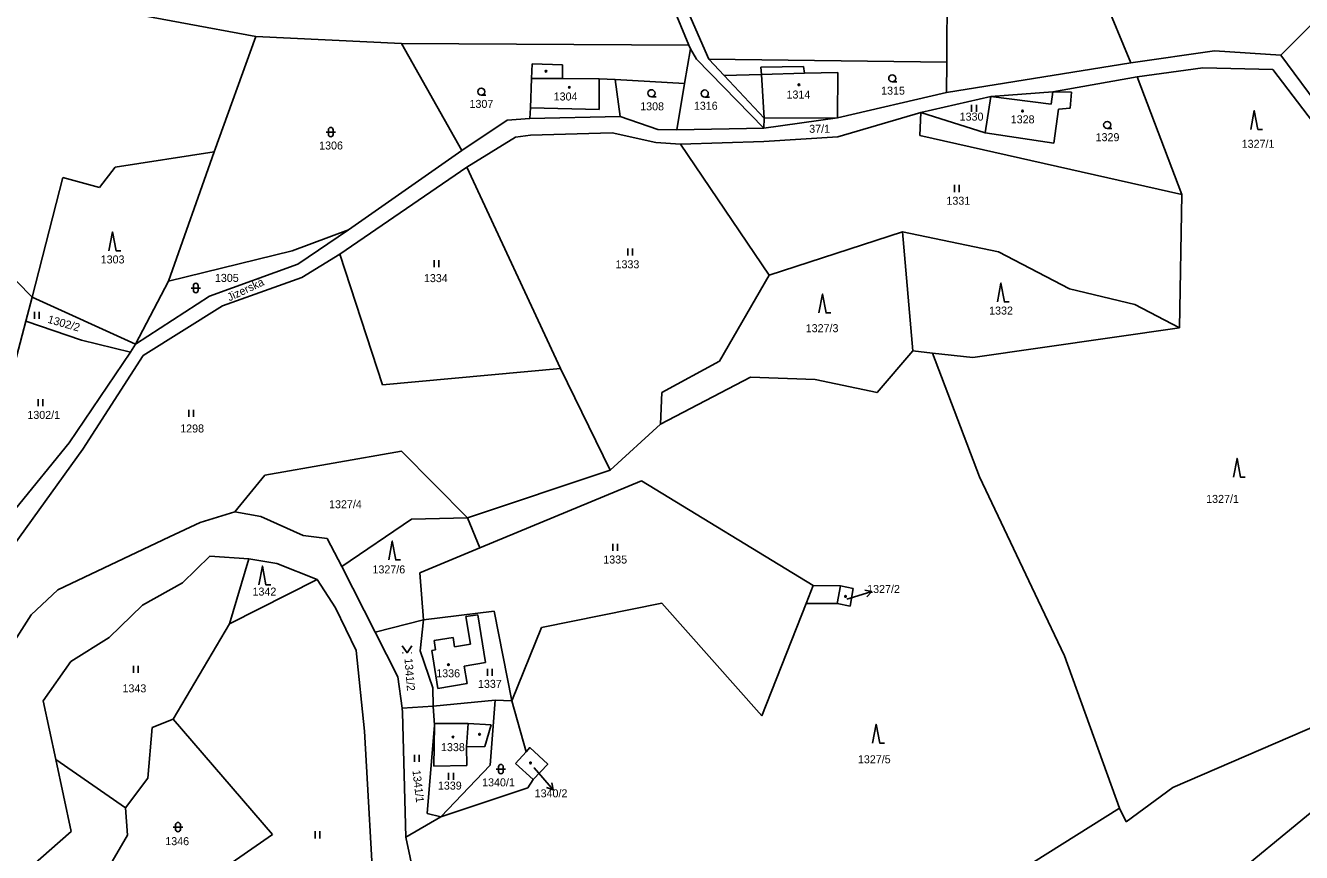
# Model space of a CAD drawing. Extents: x -670359 to -668019, y -978807 to -976674.
# Drawn here: x -669846.5 to -669575.5, y -978118.6 to -977942.9 of the extents above; entities that cross this region are included whole.
import ezdxf

# ---------------------------------------------------------------- set-up
doc = ezdxf.new("R2010")
doc.units = 0
for name, color, linetype in [('Hranice parcel', 7, 'Continuous'), ('Parcelní čísla', 7, 'Continuous'), ('Pop  PČ popisy', 7, 'Continuous'), ('Vnitřní kresba', 7, 'Continuous'), ('Značky budov', 7, 'Continuous'), ('Značky kultur', 7, 'Continuous')]:
    doc.layers.add(name, color=color, linetype=linetype)

msp = doc.modelspace()

# ---------------------------------------------------------------- linework, layer by layer
at = {"layer": 'Hranice parcel'}
for p, q in [((-669749.99, -978053.86), (-669715.71, -978039.65)), ((-669749.99, -978053.86), (-669752.65, -978047.5)), ((-669762.74, -978059.14), (-669749.99, -978053.86)), ((-669752.97, -978068.48), (-669750.42, -978068.07)), ((-669751.98, -978074.33), (-669752.97, -978068.48)), ((-669750.42, -978068.07), (-669748.8, -978078.23)), ((-669759.75, -978073.55), (-669755.71, -978072.94)), ((-669759.43, -978075.56), (-669759.75, -978073.55)), ((-669755.71, -978072.94), (-669755.39, -978074.89)), ((-669755.39, -978074.89), (-669751.98, -978074.33)), ((-669759.43, -978075.56), (-669760.25, -978075.66)), ((-669760.25, -978075.66), (-669758.93, -978083.72)), ((-669748.8, -978078.23), (-669753.36, -978079.01)), ((-669753.36, -978079.01), (-669752.75, -978082.68)), ((-669752.75, -978082.68), (-669758.93, -978083.72))]:
    msp.add_line(p, q, dxfattribs=at)
for points in [[(-669715.01, -977924.37), (-669705.6, -977947.07)], [(-669712.05, -977925.47), (-669701.36, -977950.02)], [(-669561.67, -977930.85), (-669579.87, -977949.13)], [(-669650.74, -977934.54), (-669650.81, -977950.68)], [(-669617.62, -977936.58), (-669611.71, -977950.77)], [(-669829.77, -977939.28), (-669797.59, -977945.16)], [(-669806.49, -977969.67), (-669797.59, -977945.16)], [(-669797.59, -977945.16), (-669766.63, -977946.66)], [(-669753.87, -977969.43), (-669766.63, -977946.66)], [(-669766.63, -977946.66), (-669705.6, -977947.07)], [(-669705.29, -977947.81), (-669705.6, -977947.07)], [(-669706.53, -977955.17), (-669705.29, -977947.81)], [(-669704, -977950.04), (-669705.29, -977947.81)], [(-669689.68, -977964.66), (-669704, -977950.04)], [(-669701.36, -977950.02), (-669698.1, -977953.5)], [(-669650.81, -977950.68), (-669701.36, -977950.02)], [(-669593.97, -977948.26), (-669611.71, -977950.77)], [(-669579.87, -977949.13), (-669593.97, -977948.26)], [(-669579.87, -977949.13), (-669571.19, -977960.9)], [(-669739.05, -977954.1), (-669738.94, -977950.97)], [(-669738.94, -977950.97), (-669732.46, -977951.25)], [(-669732.44, -977954.12), (-669732.46, -977951.25)], [(-669681.28, -977951.58), (-669690.31, -977951.71)], [(-669690.31, -977951.71), (-669690.21, -977953.28)], [(-669681.03, -977953.02), (-669681.28, -977951.58)], [(-669673.99, -977952.82), (-669681.03, -977953.02)], [(-669674.02, -977962.49), (-669673.99, -977952.82)], [(-669650.86, -977957.07), (-669650.81, -977950.68)], [(-669611.71, -977950.77), (-669650.86, -977957.07)], [(-669596.43, -977951.87), (-669610.41, -977953.79)], [(-669581.59, -977952.23), (-669596.43, -977951.87)], [(-669581.59, -977952.23), (-669572.03, -977964.73)], [(-669739.29, -977960.32), (-669739.05, -977954.1)], [(-669724.69, -977954.16), (-669732.44, -977954.12)], [(-669721.25, -977954.3), (-669724.69, -977954.16)], [(-669720.24, -977962.2), (-669721.25, -977954.3)], [(-669721.25, -977954.3), (-669706.53, -977955.17)], [(-669708.15, -977965.01), (-669706.53, -977955.17)], [(-669690.21, -977953.28), (-669698.1, -977953.5)], [(-669698.1, -977953.5), (-669689.61, -977962.58)], [(-669610.41, -977953.79), (-669628.31, -977956.94)], [(-669610.41, -977953.79), (-669600.92, -977978.75)], [(-669650.86, -977957.07), (-669674.02, -977962.49)], [(-669641.5, -977957.98), (-669656.35, -977961.34)], [(-669641.5, -977957.98), (-669642.65, -977965.65)], [(-669628.31, -977956.94), (-669641.5, -977957.98)], [(-669628.31, -977956.94), (-669624.31, -977956.99)], [(-669624.31, -977956.99), (-669624.61, -977960.43)], [(-669739.43, -977962.64), (-669739.29, -977960.32)], [(-669627.09, -977960.61), (-669628.09, -977967.88)], [(-669624.61, -977960.43), (-669627.09, -977960.61)], [(-669744.23, -977962.98), (-669753.87, -977969.43)], [(-669739.43, -977962.64), (-669744.23, -977962.98)], [(-669720.24, -977962.2), (-669739.43, -977962.64)], [(-669712.23, -977964.95), (-669720.24, -977962.2)], [(-669674.02, -977962.49), (-669689.68, -977964.66)], [(-669689.61, -977962.58), (-669689.68, -977964.66)], [(-669656.35, -977961.34), (-669674, -977966.5)], [(-669656.35, -977961.34), (-669656.57, -977966.22)], [(-669642.65, -977965.65), (-669656.35, -977961.34)], [(-669739.26, -977966.15), (-669742.45, -977966.57)], [(-669721.9, -977965.65), (-669739.26, -977966.15)], [(-669712.62, -977967.75), (-669721.9, -977965.65)], [(-669708.15, -977965.01), (-669712.23, -977964.95)], [(-669689.68, -977964.66), (-669708.15, -977965.01)], [(-669674, -977966.5), (-669689.67, -977967.53)], [(-669656.57, -977966.22), (-669600.92, -977978.75)], [(-669628.09, -977967.88), (-669642.65, -977965.65)], [(-669742.45, -977966.57), (-669752.81, -977972.94)], [(-669707.42, -977968.04), (-669712.62, -977967.75)], [(-669689.67, -977967.53), (-669707.42, -977968.04)], [(-669707.42, -977968.04), (-669688.55, -977995.9)], [(-669845.11, -978000.59), (-669874.62, -977970.47)], [(-669806.49, -977969.67), (-669827.51, -977972.99)], [(-669816.18, -977997.22), (-669806.49, -977969.67)], [(-669753.87, -977969.43), (-669777.93, -977986.28)], [(-669827.51, -977972.99), (-669830.84, -977977.25)], [(-669752.81, -977972.94), (-669779.74, -977991.48)], [(-669752.81, -977972.94), (-669732.91, -978015.74)], [(-669838.61, -977975.13), (-669845.11, -978000.59)], [(-669830.84, -977977.25), (-669838.61, -977975.13)], [(-669600.92, -977978.75), (-669601.41, -978007.12)], [(-669777.93, -977986.28), (-669789.9, -977990.75)], [(-669777.93, -977986.28), (-669788.69, -977993.54)], [(-669660.21, -977986.7), (-669688.55, -977995.9)], [(-669639.88, -977990.97), (-669660.21, -977986.7)], [(-669658.08, -978012.02), (-669660.21, -977986.7)], [(-669789.9, -977990.75), (-669816.18, -977997.22)], [(-669788.69, -977993.54), (-669807.45, -978000.36)], [(-669779.74, -977991.48), (-669787.87, -977996.41)], [(-669779.74, -977991.48), (-669770.72, -978019.24)], [(-669624.8, -977998.79), (-669639.88, -977990.97)], [(-669688.55, -977995.9), (-669699.09, -978014.18)], [(-669816.18, -977997.22), (-669823.14, -978010.6)], [(-669787.87, -977996.41), (-669804.72, -978002.42)], [(-669610.87, -978002.14), (-669624.8, -977998.79)], [(-669845.11, -978000.59), (-669846.46, -978005.72)], [(-669823.14, -978010.6), (-669845.11, -978000.59)], [(-669807.45, -978000.36), (-669823.14, -978010.6)], [(-669804.72, -978002.42), (-669821.53, -978012.99)], [(-669601.41, -978007.12), (-669610.87, -978002.14)], [(-669851.14, -978023.56), (-669846.46, -978005.72)], [(-669846.46, -978005.72), (-669834.63, -978009.76)], [(-669601.41, -978007.12), (-669645.28, -978013.38)], [(-669834.63, -978009.76), (-669824.26, -978012.26)], [(-669837.27, -978031.54), (-669824.26, -978012.26)], [(-669823.14, -978010.6), (-669824.26, -978012.26)], [(-669711.65, -978027.6), (-669692.55, -978017.59), (-669678.77, -978018.11), (-669665.64, -978020.88), (-669658.08, -978012.02)], [(-669653.9, -978012.46), (-669658.08, -978012.02)], [(-669653.9, -978012.46), (-669643.86, -978038.78), (-669631.39, -978065.02), (-669625.82, -978076.84), (-669614.14, -978109.21)], [(-669645.28, -978013.38), (-669653.9, -978012.46)], [(-669821.53, -978012.99), (-669834.38, -978032.89)], [(-669699.09, -978014.18), (-669711.37, -978020.88)], [(-669770.72, -978019.24), (-669732.91, -978015.74)], [(-669732.91, -978015.74), (-669722.32, -978037.33)], [(-669711.37, -978020.88), (-669711.65, -978027.6)], [(-669711.65, -978027.6), (-669722.32, -978037.33)], [(-669837.27, -978031.54), (-669848.63, -978045.6)], [(-669834.38, -978032.89), (-669849.06, -978053.35)], [(-669766.64, -978033.28), (-669795.72, -978038.41)], [(-669752.65, -978047.5), (-669766.64, -978033.28)], [(-669795.72, -978038.41), (-669802.07, -978046.23)], [(-669722.32, -978037.33), (-669752.65, -978047.5)], [(-669679.2, -978061.88), (-669715.71, -978039.65)], [(-669802.07, -978046.23), (-669809.46, -978048.47)], [(-669796.55, -978047.17), (-669802.07, -978046.23)], [(-669787.55, -978051.27), (-669796.55, -978047.17)], [(-669779.37, -978057.85), (-669764.54, -978047.77), (-669752.65, -978047.5)], [(-669809.46, -978048.47), (-669815.97, -978051.52)], [(-669815.97, -978051.52), (-669839.7, -978062.78)], [(-669782.45, -978051.84), (-669787.55, -978051.27)], [(-669779.37, -978057.85), (-669782.45, -978051.84)], [(-669807.37, -978055.61), (-669813.19, -978061.31)], [(-669799.06, -978056.2), (-669807.37, -978055.61)], [(-669799.06, -978056.2), (-669803.2, -978069.98)], [(-669799.06, -978056.2), (-669793.15, -978057.15)], [(-669793.15, -978057.15), (-669784.55, -978060.55)], [(-669772.24, -978071.75), (-669779.37, -978057.85)], [(-669813.19, -978061.31), (-669821.65, -978066.02)], [(-669803.2, -978069.98), (-669784.55, -978060.55)], [(-669784.55, -978060.55), (-669780.68, -978066.64)], [(-669762.74, -978059.14), (-669761.97, -978069.19)], [(-669839.7, -978062.78), (-669845.36, -978068.08)], [(-669679.2, -978061.88), (-669680.7, -978065.69)], [(-669673.42, -978061.91), (-669679.2, -978061.88)], [(-669670.69, -978062.49), (-669673.42, -978061.91)], [(-669671.36, -978066.28), (-669670.69, -978062.49)], [(-669821.65, -978066.02), (-669828.77, -978072.9)], [(-669780.68, -978066.64), (-669776.32, -978075.66)], [(-669736.93, -978070.77), (-669711.34, -978065.61)], [(-669711.34, -978065.61), (-669690.14, -978089.59)], [(-669690.14, -978089.59), (-669680.7, -978065.69)], [(-669680.7, -978065.69), (-669674.13, -978065.72)], [(-669674.13, -978065.72), (-669671.36, -978066.28)], [(-669845.36, -978068.08), (-669851.96, -978078.41)], [(-669761.97, -978069.19), (-669772.24, -978071.75)], [(-669762.68, -978075.77), (-669761.97, -978069.19)], [(-669746.97, -978067.31), (-669761.97, -978069.19)], [(-669743.25, -978086.36), (-669746.97, -978067.31)], [(-669803.2, -978069.98), (-669815.18, -978090.24)], [(-669767.46, -978081.24), (-669772.24, -978071.75)], [(-669743.25, -978086.36), (-669736.93, -978070.77)], [(-669828.77, -978072.9), (-669836.9, -978078.01)], [(-669776.32, -978075.66), (-669774.52, -978092.81)], [(-669760.04, -978083.6), (-669762.68, -978075.77)], [(-669836.9, -978078.01), (-669842.76, -978086.35)], [(-669767.46, -978081.24), (-669766.54, -978087.96)], [(-669759.96, -978087.51), (-669760.04, -978083.6)], [(-669842.76, -978086.35), (-669840.09, -978098.85)], [(-669759.96, -978087.51), (-669766.54, -978087.96)], [(-669766.42, -978088.85), (-669766.54, -978087.96)], [(-669746.78, -978086.26), (-669759.96, -978087.51)], [(-669759.68, -978091.53), (-669759.96, -978087.51)], [(-669747.8, -978100.01), (-669746.78, -978086.26)], [(-669743.25, -978086.36), (-669746.78, -978086.26)], [(-669740.21, -978097.19), (-669743.25, -978086.36)], [(-669815.18, -978090.24), (-669819.6, -978092.03)], [(-669815.18, -978090.24), (-669794.07, -978114.79)], [(-669765.74, -978115.32), (-669766.42, -978088.85)], [(-669759.64, -978091.16), (-669759.68, -978091.53)], [(-669759.64, -978091.16), (-669752.51, -978091.16)], [(-669752.51, -978091.16), (-669747.6, -978091.5)], [(-669565.41, -978088.62), (-669602.81, -978104.77)], [(-669819.6, -978092.03), (-669820.52, -978102.82)], [(-669774.52, -978092.81), (-669772.32, -978131.64)], [(-669761.2, -978110.34), (-669759.68, -978091.53)], [(-669759.77, -978100.22), (-669759.68, -978091.53)], [(-669747.6, -978091.5), (-669748.93, -978096.06)], [(-669748.93, -978096.06), (-669752.83, -978096.11)], [(-669752.83, -978096.11), (-669752.77, -978100.11)], [(-669740.21, -978097.19), (-669739.43, -978096.32), (-669735.61, -978099.85), (-669738.71, -978103.12)], [(-669840.09, -978098.85), (-669836.81, -978114.16)], [(-669840.09, -978098.85), (-669825.3, -978109.09)], [(-669742.48, -978099.72), (-669740.21, -978097.19)], [(-669558.06, -978097.42), (-669639.86, -978164.68)], [(-669752.77, -978100.11), (-669759.77, -978100.22)], [(-669758.34, -978111.02), (-669747.8, -978100.01)], [(-669738.71, -978103.12), (-669742.48, -978099.72)], [(-669820.52, -978102.82), (-669825.3, -978109.09)], [(-669739.85, -978104.89), (-669738.71, -978103.12)], [(-669758.34, -978111.02), (-669739.85, -978104.89)], [(-669602.81, -978104.77), (-669612.73, -978112.1)], [(-669825.3, -978109.09), (-669824.89, -978114.93)], [(-669614.14, -978109.21), (-669678.12, -978149.31)], [(-669612.73, -978112.1), (-669614.14, -978109.21)], [(-669765.74, -978115.32), (-669758.34, -978111.02)], [(-669758.34, -978111.02), (-669761.2, -978110.34)], [(-669794.07, -978114.79), (-669845.64, -978150.52)], [(-669824.89, -978114.93), (-669845.64, -978150.52)], [(-669836.81, -978114.16), (-669845.61, -978121.83)], [(-669761.6, -978134.99), (-669765.74, -978115.32)]]:
    msp.add_lwpolyline(points, dxfattribs=at)
at = {"layer": 'Parcelní čísla'}
for p, q in [((-669668.26, -978062.82), (-669666.79, -978063.15)), ((-669672.05, -978064.76), (-669670.62, -978064.32)), ((-669738.45, -978100.63), (-669737.05, -978102.24)), ((-669734.71, -978103.79), (-669734.43, -978105.26))]:
    msp.add_line(p, q, dxfattribs=at)
for points in [[(-669670.62, -978064.32), (-669666.79, -978063.15), (-669667.82, -978064.25)], [(-669737.05, -978102.24), (-669734.43, -978105.26), (-669735.85, -978104.77)]]:
    msp.add_lwpolyline(points, dxfattribs=at)
at = {"layer": 'Vnitřní kresba'}
for points in [[(-669739.05, -977954.1), (-669732.44, -977954.12)], [(-669724.69, -977954.16), (-669724.65, -977960.71)], [(-669690.21, -977953.28), (-669681.03, -977953.02)], [(-669689.61, -977962.58), (-669690.21, -977953.28)], [(-669641.5, -977957.98), (-669628.69, -977959.58)], [(-669628.69, -977959.58), (-669628.31, -977956.94)], [(-669724.65, -977960.71), (-669739.29, -977960.32)], [(-669689.61, -977962.58), (-669674.02, -977962.49)], [(-669674.13, -978065.72), (-669673.42, -978061.91)], [(-669752.51, -978091.16), (-669752.83, -978096.11)]]:
    msp.add_lwpolyline(points, dxfattribs=at)
at = {"layer": 'Značky budov'}
for centre in [(-669682.25, -977955.45), (-669731.01, -977956), (-669634.75, -977961.05), (-669672.35, -978064.19), (-669756.69, -978078.67), (-669755.73, -978094.07), (-669739.26, -978099.55)]:
    msp.add_circle(centre, 0.175, dxfattribs=at)
at = {"layer": 'Značky kultur'}
for p, q in [((-669662.42, -977954.85), (-669661.42, -977954.85)), ((-669749.72, -977957.67), (-669748.72, -977957.67)), ((-669713.56, -977958), (-669712.56, -977958)), ((-669702.24, -977958.06), (-669701.24, -977958.06)), ((-669645.55, -977959.69), (-669645.55, -977961.19)), ((-669644.55, -977961.19), (-669644.55, -977959.69)), ((-669782.7, -977965.51), (-669780.7, -977965.51)), ((-669782.2, -977965.01), (-669782.2, -977966.01)), ((-669781.2, -977965.01), (-669781.2, -977966.01)), ((-669616.76, -977964.74), (-669615.76, -977964.74)), ((-669649.23, -977976.74), (-669649.23, -977978.24)), ((-669648.23, -977978.24), (-669648.23, -977976.74)), ((-669718.59, -977990.25), (-669718.59, -977991.75)), ((-669717.59, -977991.75), (-669717.59, -977990.25)), ((-669759.76, -977992.7), (-669759.76, -977994.2)), ((-669758.76, -977994.2), (-669758.76, -977992.7)), ((-669811.36, -977998.64), (-669809.36, -977998.64)), ((-669810.86, -977998.14), (-669810.86, -977999.14)), ((-669809.86, -977998.14), (-669809.86, -977999.14)), ((-669844.61, -978003.71), (-669844.61, -978005.21)), ((-669843.61, -978005.21), (-669843.61, -978003.71)), ((-669843.82, -978022.23), (-669843.82, -978023.73)), ((-669842.82, -978023.73), (-669842.82, -978022.23)), ((-669811.87, -978024.54), (-669811.87, -978026.04)), ((-669810.87, -978026.04), (-669810.87, -978024.54)), ((-669721.8, -978052.99), (-669721.8, -978054.49)), ((-669720.8, -978054.49), (-669720.8, -978052.99)), ((-669766.44, -978076.15), (-669766.34, -978076.15)), ((-669764.64, -978076.15), (-669764.54, -978076.15)), ((-669823.57, -978078.93), (-669823.57, -978080.43)), ((-669822.57, -978080.43), (-669822.57, -978078.93)), ((-669748.38, -978079.59), (-669748.38, -978081.09)), ((-669747.38, -978081.09), (-669747.38, -978079.59)), ((-669763.88, -978097.81), (-669763.88, -978099.31)), ((-669762.88, -978099.31), (-669762.88, -978097.81)), ((-669756.65, -978101.64), (-669756.65, -978103.14)), ((-669755.65, -978103.14), (-669755.65, -978101.64)), ((-669746.55, -978100.87), (-669744.55, -978100.87)), ((-669746.05, -978100.37), (-669746.05, -978101.37)), ((-669745.05, -978100.37), (-669745.05, -978101.37)), ((-669814.64, -978112.71), (-669814.64, -978113.71)), ((-669813.64, -978112.71), (-669813.64, -978113.71)), ((-669815.14, -978113.21), (-669813.14, -978113.21)), ((-669785.03, -978114.09), (-669785.03, -978115.59)), ((-669784.03, -978115.59), (-669784.03, -978114.09))]:
    msp.add_line(p, q, dxfattribs=at)
for points in [[(-669586.26, -977964.93), (-669585.51, -977960.93), (-669584.76, -977964.93), (-669583.76, -977964.93)], [(-669828.81, -977990.72), (-669828.06, -977986.72), (-669827.31, -977990.72), (-669826.31, -977990.72)], [(-669640.09, -978001.59), (-669639.34, -977997.59), (-669638.59, -978001.59), (-669637.59, -978001.59)], [(-669677.98, -978003.93), (-669677.23, -977999.93), (-669676.48, -978003.93), (-669675.48, -978003.93)], [(-669589.93, -978038.87), (-669589.18, -978034.87), (-669588.43, -978038.87), (-669587.43, -978038.87)], [(-669769.37, -978056.43), (-669768.62, -978052.43), (-669767.87, -978056.43), (-669766.87, -978056.43)], [(-669796.95, -978061.73), (-669796.2, -978057.73), (-669795.45, -978061.73), (-669794.45, -978061.73)], [(-669766.49, -978074.65), (-669765.49, -978076.15), (-669764.49, -978074.65)], [(-669666.59, -978095.33), (-669665.84, -978091.33), (-669665.09, -978095.33), (-669664.09, -978095.33)]]:
    msp.add_lwpolyline(points, dxfattribs=at)
for centre, radius in [((-669735.96, -977952.57), 0.175), ((-669682.25, -977955.45), 0.175), ((-669662.42, -977954.1), 0.75), ((-669749.72, -977956.92), 0.75), ((-669731.01, -977956), 0.175), ((-669713.56, -977957.25), 0.75), ((-669702.24, -977957.31), 0.75), ((-669634.75, -977961.05), 0.175), ((-669616.76, -977963.99), 0.75), ((-669672.35, -978064.19), 0.175), ((-669756.69, -978078.67), 0.175), ((-669755.73, -978094.07), 0.175), ((-669750.09, -978093.48), 0.175), ((-669739.26, -978099.55), 0.175)]:
    msp.add_circle(centre, radius, dxfattribs=at)
for centre, start, end in [((-669781.7, -977965.01), 0, 180), ((-669781.7, -977966.01), 180, 0), ((-669810.36, -977998.14), 0, 180), ((-669810.36, -977999.14), 180, 0), ((-669745.55, -978100.37), 0, 180), ((-669745.55, -978101.37), 180, 0), ((-669814.14, -978112.71), 0, 180), ((-669814.14, -978113.71), 180, 0)]:
    msp.add_arc(centre, 0.5, start, end, dxfattribs=at)

# ---------------------------------------------------------------- texts
at = {"layer": 'Parcelní čísla'}
for s, height, p in [('1304', 1.7, (-669734.34, -977958.79)), ('1314', 1.7, (-669684.88, -977958.38)), ('1315', 1.7, (-669664.78, -977957.55)), ('1307', 1.7, (-669752.22, -977960.37)), ('1308', 1.7, (-669715.96, -977960.89)), ('1316', 1.7, (-669704.56, -977960.76)), ('1330', 1.7, (-669648.1, -977963.07)), ('1328', 1.7, (-669637.25, -977963.65)), ('37/1', 1.7, (-669680.06, -977965.66)), ('1329', 1.7, (-669619.22, -977967.44)), ('1306', 1.7, (-669784.16, -977969.21)), ('1327/1', 1.7, (-669588.19, -977968.85)), ('1331', 1.7, (-669650.91, -977980.94)), ('1303', 1.7, (-669830.56, -977993.42)), ('1333', 1.7, (-669721.2, -977994.45)), ('1305', 1.7, (-669806.3, -977997.34)), ('1334', 1.7, (-669761.9, -977997.39)), ('1332', 1.7, (-669641.84, -978004.29)), ('1327/3', 1.7, (-669680.8, -978008.03)), ('1302/1', 1.7, (-669846.14, -978026.46)), ('1298', 1.7, (-669813.67, -978029.34)), ('1327/4', 1.7, (-669782.05, -978045.44)), ('1327/1', 1.7, (-669595.74, -978044.31)), ('1335', 1.7, (-669723.8, -978057.19)), ('1327/6', 1.7, (-669772.83, -978059.29)), ('1342', 1.7, (-669798.31, -978064)), ('1327/2', 1.7, (-669667.75, -978063.45)), ('1327/2', 0.1, (-669672.05, -978064.76)), ('1336', 1.7, (-669759.28, -978081.37)), ('1343', 1.7, (-669825.93, -978084.57)), ('1337', 1.7, (-669750.42, -978083.61)), ('1338', 1.7, (-669758.27, -978097.06)), ('1327/5', 1.7, (-669669.71, -978099.64)), ('1340/2', 0.1, (-669738.69, -978100.63)), ('1339', 1.7, (-669758.93, -978105.23)), ('1340/1', 1.7, (-669749.54, -978104.54)), ('1340/2', 1.7, (-669738.38, -978106.87)), ('1346', 1.7, (-669816.84, -978117.04))]:
    msp.add_text(s, height=height, dxfattribs=at).set_placement(p)
for s, rotation, p in [('1302/2', 344.0138, (-669841.95, -978006)), ('1341/2', 274.6355, (-669766.03, -978077.39)), ('1341/1', 276.6544, (-669764.34, -978101.17))]:
    msp.add_text(s, height=1.7, rotation=rotation, dxfattribs=at).set_placement(p)
at = {"layer": 'Pop  PČ popisy'}
msp.add_text('Jizerská', height=1.7, rotation=25.1723, dxfattribs=at).set_placement((-669803.22, -978001.5))

doc.saveas('drawing.dxf')
